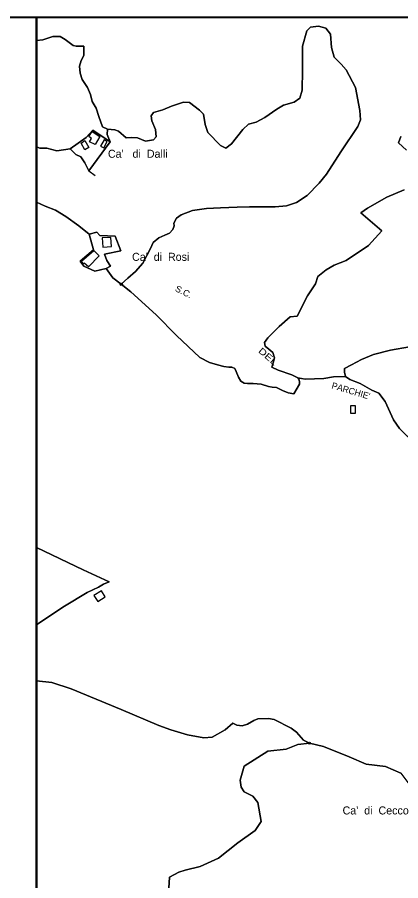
# Model space of a CAD drawing. Extents: x 650468 to 655025, y 889970 to 891591.
# Drawn here: x 653594 to 654074, y 890512 to 891591 of the extents above; entities that cross this region are included whole.
import ezdxf
from ezdxf.enums import TextEntityAlignment as Align

# ---------------------------------------------------------------- set-up
doc = ezdxf.new("R2010")
doc.units = 0
doc.header["$LTSCALE"] = 5.6
doc.header["$PDMODE"] = 32
doc.header["$PDSIZE"] = 2.8
for name, color, linetype, lineweight in [('2', 7, 'Continuous', 25), ('35', 7, 'Continuous', 25), ('36', 7, 'Continuous', 25), ('37', 7, 'Continuous', 25), ('6', 7, 'Continuous', 25), ('61', 7, 'Continuous', 35)]:
    doc.layers.add(name, color=color, linetype=linetype, lineweight=lineweight)
doc.layers.add('60', color=7, linetype='Continuous')

msp = doc.modelspace()

# ---------------------------------------------------------------- linework, layer by layer
at = {"layer": '2'}
for points in [[(653673.57, 891416.45), (653678.66, 891409.08), (653683.47, 891399.15), (653710.23, 891435.25), (653688.69, 891450.13), (653680.38, 891440.64), (653660.36, 891426.81), (653667.27, 891419.45)], [(653683.55, 891441.89), (653687.64, 891448.36), (653697.47, 891442.19), (653691.48, 891431.96), (653684.6, 891435.36), (653686.7, 891439.4)], [(653678.65, 891436.86), (653683.42, 891428.33), (653678.65, 891425.24), (653673.81, 891433.77)], [(653702.8, 891438.01), (653698.29, 891429.97), (653702.15, 891427.86), (653706.43, 891435.83)], [(653700.22, 891315.25), (653701, 891303.93), (653711.74, 891304.65), (653711.13, 891315.64)], [(653689.69, 891299.64), (653696.5, 891292.71), (653683.12, 891279.08), (653677.9, 891283.75), (653677.1, 891282.92), (653674.2, 891286.3)]]:
    msp.add_lwpolyline(points, close=True, dxfattribs=at)
for points in [[(653716.57, 891317.55), (653697.34, 891318.4), (653693.43, 891322.32), (653684.02, 891319.96)], [(653684.02, 891319.96), (653689.25, 891300.36), (653672.79, 891286.24), (653677.47, 891279.85), (653690.97, 891273.65), (653705.37, 891277.05), (653710.67, 891280.15), (653706.27, 891286.95), (653703.07, 891295.15), (653723.73, 891299.05), (653716.57, 891317.55)]]:
    msp.add_lwpolyline(points, dxfattribs=at)
at = {"layer": '35'}
msp.add_lwpolyline([(654084.85, 891179.05), (654060.75, 891174.83), (654039.66, 891169.4), (654024.6, 891163.37), (654011.94, 891156.74), (654003.51, 891151.92), (654003.16, 891147.66), (654004.69, 891141.92), (654010.04, 891138.49), (654023.02, 891133.14), (654037.53, 891125.11), (654046.31, 891121.29), (654054.33, 891110.98), (654064.64, 891088.06), (654072.27, 891076.98), (654082.2, 891067.04)], dxfattribs=at)
msp.add_lwpolyline([(653618.27, 890831.56), (653632.13, 890841.1), (653653.19, 890855.2), (653681.51, 890872.22), (653695.46, 890878.92), (653702.04, 890882.5), (653709.07, 890885.64), (653676.42, 890900.31), (653618.27, 890928.35)], close=True, dxfattribs=at)
at = {"layer": '36'}
for points in [[(654180.27, 891591.08), (653618.27, 891591.08)], [(653618.27, 891591.08), (653618.27, 891561.91), (653626.06, 891562.98), (653638.51, 891567.01), (653647.84, 891567.01), (653654.07, 891563.49), (653663.92, 891555.94), (653667.55, 891554.93), (653677.21, 891555.07), (653677.21, 891543.5), (653674.1, 891536.96), (653672.02, 891529.91), (653672.54, 891521.36), (653675.13, 891513.31), (653681.87, 891503.25), (653685.5, 891494.69), (653687.58, 891485.64), (653692.76, 891477.59), (653696.28, 891467.23), (653700.76, 891454.04), (653706.98, 891451.05), (653715.93, 891450.55), (653720.77, 891448.91), (653730.1, 891440.35), (653736.32, 891440.86), (653744.62, 891440.35), (653754.47, 891436.33), (653764.33, 891437.84), (653767.91, 891441.84), (653766.92, 891450.92), (653762.25, 891461.49), (653761.73, 891468.03), (653764.33, 891472.05), (653776.25, 891475.57), (653787.14, 891480.1), (653802.18, 891485.13), (653809.44, 891484.63), (653821.89, 891475.07), (653827.07, 891470.04), (653829.15, 891456.96)], [(653829.15, 891456.96), (653832.26, 891446.9), (653848.34, 891430.79), (653855.08, 891427.27), (653861.82, 891432.81), (653876.34, 891450.92), (653883.08, 891457.46), (653892.93, 891459.98), (653903.82, 891466.01), (653918.86, 891476.08), (653927.16, 891481.11), (653940.57, 891485.02), (653947.31, 891490.05), (653950.42, 891500.11), (653950.94, 891524.77), (653950.94, 891554.95), (653956.12, 891574.07), (653960.79, 891578.6), (653970.64, 891580.11), (653979.98, 891577.59), (653985.68, 891570.05), (653987.24, 891553.44), (653990.35, 891541.37), (653999.17, 891532.31), (654005.39, 891525.27), (654017.32, 891503.13), (654022.51, 891474.63), (654023.55, 891463.05), (654019.92, 891454.5), (653998.66, 891422.8), (653981.03, 891395.13), (653971.74, 891383.73), (653956.7, 891368.14), (653943.22, 891359.58), (653930.77, 891355.56), (653916.77, 891354.05), (653902.25, 891354.05), (653884.62, 891354.05), (653869.06, 891353.55), (653848.32, 891353.04)], [(654080.73, 891424.8), (654070.84, 891434.15), (654073.82, 891441.86)], [(653935.54, 891216.61), (653944.25, 891217.61), (653956.94, 891242.75), (653966.97, 891257.92), (653970.12, 891267.14), (653980.32, 891275.6), (653990.27, 891281.32), (654005.44, 891287.05), (654033.54, 891305.96), (654049.9, 891324.12), (654023.61, 891346.5), (654032.16, 891352.42), (654056.47, 891366.24), (654078.16, 891375.45)], [(653848.32, 891353.04), (653830.69, 891352.04), (653813.06, 891349.52), (653799.05, 891343.99), (653793.35, 891339.96), (653789.72, 891333.92), (653790.24, 891330.4), (653788.68, 891325.87), (653784.53, 891321.35), (653778.83, 891318.83), (653771.05, 891315.31), (653764.21, 891309.49), (653760.58, 891301.94), (653751.25, 891283.83), (653741.91, 891273.26), (653732.4, 891264.91), (653724.1, 891257.3), (653736.11, 891247.91), (653767.66, 891218.95), (653793.29, 891193.29), (653822.21, 891165.65), (653834.52, 891159.66), (653844.57, 891156.66), (653852.56, 891154.41), (653858.48, 891153.91), (653862.6, 891153.66), (653866.21, 891151.91), (653868.01, 891148.41), (653870.59, 891141.41), (653873.68, 891136.16), (653877.8, 891133.91), (653882.18, 891133.16), (653889.14, 891133.16), (653899.19, 891132.41), (653908.21, 891129.41), (653912.84, 891128.91), (653918.25, 891128.41), (653925.98, 891124.41), (653932.94, 891121.66), (653940.04, 891120.48)], [(653940.04, 891120.48), (653947.23, 891132.4), (653947.23, 891135.93), (653946.33, 891138.55), (653945.13, 891140.59), (653937.62, 891144.09), (653920.51, 891150.2), (653912.46, 891153.63), (653913.96, 891159.1), (653915.63, 891165.59), (653913.56, 891172.13), (653908.89, 891176.16), (653904.23, 891180.18), (653903.19, 891184.71), (653907.34, 891190.24), (653921.62, 891204.42), (653935.54, 891216.61)], [(653786.19, 890700.26), (653771.25, 890705.76), (653723.84, 890725.75), (653661.66, 890751.68), (653637.45, 890759.68), (653618.27, 890761.81), (653618.27, 890249.95)], [(653783.48, 890502.65), (653784.27, 890516.11), (653795.96, 890522.54), (653804.2, 890525.04), (653823.01, 890529.82), (653845.68, 890539.84), (653870.14, 890559.32), (653891.81, 890574.66), (653899.19, 890586), (653894.97, 890609.74), (653888.53, 890617.66), (653878.02, 890622.93), (653874.07, 890628.85), (653872.76, 890637.4), (653878.02, 890655.17), (653907.6, 890673.6), (653930.6, 890676.23), (653945.06, 890682.15), (653959.44, 890683.82), (653952.13, 890687.71), (653943.24, 890697.52), (653936.47, 890702.48), (653915.28, 890713.18), (653908.47, 890714.71), (653894.98, 890714.18), (653889.97, 890712.23), (653882.05, 890707.5), (653875.38, 890705.34), (653868.68, 890706.1), (653863.67, 890708.72), (653854.21, 890700.26), (653837.72, 890691.26), (653827.41, 890690.26), (653806.8, 890694.26), (653786.19, 890700.26)]]:
    msp.add_lwpolyline(points, dxfattribs=at)
at = {"layer": '37'}
msp.add_line((653683.47, 891399.14), (653691.34, 891393.29), dxfattribs=at)
for points in [[(653813.06, 891349.52), (653830.69, 891352.04), (653848.32, 891353.04), (653869.06, 891353.55), (653884.62, 891354.05), (653902.25, 891354.05), (653916.77, 891354.05), (653930.77, 891355.56), (653943.22, 891359.58), (653956.7, 891368.14), (653971.74, 891383.73), (653981.03, 891395.13), (653998.66, 891422.8), (654019.92, 891454.5), (654023.55, 891463.05), (654022.51, 891474.63), (654017.32, 891503.13), (654005.39, 891525.27), (653999.17, 891532.31), (653990.35, 891541.37), (653987.24, 891553.44), (653985.68, 891570.05), (653979.98, 891577.59), (653970.64, 891580.11), (653960.79, 891578.6), (653956.12, 891574.07), (653950.94, 891554.95), (653950.94, 891524.77), (653950.42, 891500.11), (653947.31, 891490.05), (653940.57, 891485.02), (653927.16, 891481.11), (653918.86, 891476.08), (653903.82, 891466.01), (653892.93, 891459.98), (653883.08, 891457.46), (653876.34, 891450.92), (653861.82, 891432.81), (653855.08, 891427.27), (653848.34, 891430.79)], [(653710.23, 891435.24), (653706.68, 891444.44), (653706.98, 891451.05), (653700.76, 891454.04), (653696.28, 891467.23), (653692.76, 891477.59), (653687.58, 891485.64), (653685.5, 891494.69), (653681.87, 891503.25), (653675.13, 891513.31), (653672.54, 891521.36), (653672.02, 891529.91), (653674.1, 891536.96), (653677.21, 891543.5), (653677.21, 891555.07), (653667.55, 891554.93), (653663.92, 891555.94), (653654.07, 891563.49), (653647.84, 891567.01), (653638.51, 891567.01), (653626.06, 891562.98), (653618.27, 891561.91), (653618.27, 891429.1)], [(653848.34, 891430.79), (653832.26, 891446.9), (653829.15, 891456.96), (653827.07, 891470.04), (653821.89, 891475.07), (653809.44, 891484.63), (653802.18, 891485.13), (653787.14, 891480.1), (653776.25, 891475.57), (653764.33, 891472.05), (653761.73, 891468.03), (653762.25, 891461.49), (653766.92, 891450.92), (653767.91, 891441.84), (653764.33, 891437.84), (653754.47, 891436.33), (653744.62, 891440.35), (653736.32, 891440.86), (653730.1, 891440.35), (653720.77, 891448.91), (653715.93, 891450.55), (653706.98, 891451.05)], [(653630.84, 891427.39), (653643.62, 891423.98), (653660.36, 891426.8), (653680.38, 891440.63), (653688.69, 891450.12), (653710.23, 891435.24)], [(653706.98, 891451.05), (653706.68, 891444.44), (653710.23, 891435.24), (653683.47, 891399.14), (653678.66, 891409.07), (653673.57, 891416.44), (653667.27, 891419.44), (653660.36, 891426.8)], [(654073.82, 891441.86), (654070.84, 891434.15), (654080.73, 891424.8)], [(653660.36, 891426.8), (653643.62, 891423.98), (653630.84, 891427.39), (653622.32, 891427.39), (653618.27, 891429.1), (653618.27, 891360.03)], [(653618.27, 891429.1), (653622.32, 891427.39), (653630.84, 891427.39)], [(654078.16, 891375.45), (654056.47, 891366.24), (654032.16, 891352.42), (654023.61, 891346.5)], [(653618.27, 891360.03), (653629.14, 891354.92), (653641.92, 891349.8)], [(653641.92, 891349.8), (653629.14, 891354.92), (653618.27, 891360.03), (653618.27, 890928.35)], [(653641.92, 891349.8), (653654.7, 891342.13), (653670.89, 891330.19), (653684.02, 891319.95), (653693.43, 891322.31)], [(653684.02, 891319.95), (653670.89, 891330.19), (653654.7, 891342.13), (653641.92, 891349.8)], [(653705.37, 891277.04), (653713.5, 891265.39), (653724.1, 891257.3), (653732.4, 891264.91), (653741.91, 891273.26), (653751.25, 891283.83), (653760.58, 891301.94), (653764.21, 891309.49), (653771.05, 891315.31), (653778.83, 891318.83), (653784.53, 891321.35), (653788.68, 891325.87), (653790.24, 891330.4), (653789.72, 891333.92), (653793.35, 891339.96), (653799.05, 891343.99), (653813.06, 891349.52)], [(654023.61, 891346.5), (654049.9, 891324.12), (654033.54, 891305.96), (654005.44, 891287.05), (653990.27, 891281.32), (653980.32, 891275.6), (653970.12, 891267.14), (653966.97, 891257.92), (653956.94, 891242.75), (653944.25, 891217.61), (653935.54, 891216.61), (653921.62, 891204.42), (653907.34, 891190.24), (653903.19, 891184.71), (653904.23, 891180.18), (653908.89, 891176.16), (653913.56, 891172.13), (653915.63, 891165.59), (653913.96, 891159.1), (653912.46, 891153.63), (653920.51, 891150.2), (653937.62, 891144.09), (653945.13, 891140.59)], [(653693.43, 891322.31), (653697.34, 891318.39), (653716.57, 891317.54), (653723.73, 891299.04), (653703.07, 891295.14), (653706.27, 891286.94), (653710.67, 891280.14), (653705.37, 891277.04)], [(653724.1, 891257.3), (653713.5, 891265.39), (653705.37, 891277.04), (653690.97, 891273.64), (653677.47, 891279.84), (653672.79, 891286.23), (653689.25, 891300.35), (653684.02, 891319.95)], [(653705.37, 891277.04), (653713.5, 891265.39), (653724.1, 891257.3)], [(654004.69, 891141.92), (653989.79, 891141.65), (653977.45, 891139.7), (653954.29, 891138.62), (653945.13, 891140.59), (653946.33, 891138.55), (653947.23, 891135.93), (653947.23, 891132.4), (653940.04, 891120.48), (653932.94, 891121.66), (653925.98, 891124.41), (653918.25, 891128.41), (653912.84, 891128.91), (653908.21, 891129.41), (653899.19, 891132.41), (653889.14, 891133.16), (653882.18, 891133.16), (653877.8, 891133.91), (653873.68, 891136.16), (653870.59, 891141.41), (653868.01, 891148.41), (653866.21, 891151.91), (653862.6, 891153.66), (653858.48, 891153.91), (653852.56, 891154.41), (653844.57, 891156.66), (653834.52, 891159.66), (653822.21, 891165.65), (653793.29, 891193.29), (653767.66, 891218.95), (653736.11, 891247.91), (653724.1, 891257.3)], [(654004.69, 891141.92), (654003.16, 891147.66), (654003.51, 891151.92), (654011.94, 891156.74), (654024.6, 891163.37), (654039.66, 891169.4), (654060.75, 891174.83), (654084.85, 891179.05), (654102.33, 891181.46), (654118.59, 891185.08), (654130.65, 891190.5), (654143.3, 891196.53), (654154.75, 891204.37), (654169.81, 891212.81), (654180.66, 891218.84), (654198.73, 891223.66)], [(653945.13, 891140.59), (653954.29, 891138.62), (653977.45, 891139.7), (653989.79, 891141.65), (654004.69, 891141.92)], [(654092.89, 891059.02), (654082.2, 891067.04), (654072.27, 891076.98), (654064.64, 891088.06), (654054.33, 891110.98), (654046.31, 891121.29), (654037.53, 891125.11), (654023.02, 891133.14), (654010.04, 891138.49), (654004.69, 891141.92)], [(653618.27, 890928.35), (653676.42, 890900.31), (653709.07, 890885.64), (653702.04, 890882.5), (653695.46, 890878.92), (653681.51, 890872.22), (653653.19, 890855.2), (653632.13, 890841.1), (653618.27, 890831.56), (653618.27, 890761.81), (653637.45, 890759.68), (653661.66, 890751.68), (653723.84, 890725.75), (653771.25, 890705.76), (653786.19, 890700.26), (653806.8, 890694.26), (653827.41, 890690.26), (653837.72, 890691.26), (653854.21, 890700.26), (653863.67, 890708.72), (653868.68, 890706.1), (653875.38, 890705.34), (653882.05, 890707.5), (653889.97, 890712.23), (653894.98, 890714.18), (653908.47, 890714.71), (653915.28, 890713.18), (653936.47, 890702.48), (653943.24, 890697.52), (653952.13, 890687.71), (653959.44, 890683.82)], [(654073.92, 890646.45), (654054.75, 890654.53), (654030.52, 890657.56), (654009.33, 890666.64), (653977.03, 890679.77), (653959.44, 890683.82), (653945.06, 890682.15), (653930.6, 890676.23), (653907.6, 890673.6), (653878.02, 890655.17), (653872.76, 890637.4), (653874.07, 890628.85), (653878.02, 890622.93), (653888.53, 890617.66), (653894.97, 890609.74), (653899.19, 890586), (653891.81, 890574.66), (653870.14, 890559.32), (653845.68, 890539.84), (653823.01, 890529.82), (653804.2, 890525.04), (653795.96, 890522.54), (653784.27, 890516.11), (653783.48, 890502.65)], [(653959.44, 890683.82), (653977.03, 890679.77), (654009.33, 890666.64), (654030.52, 890657.56), (654054.75, 890654.53), (654073.92, 890646.45), (654085.02, 890631.3), (654097.14, 890614.13), (654111.06, 890601.43), (654122.58, 890590.55), (654129.76, 890584.43)]]:
    msp.add_lwpolyline(points, dxfattribs=at)
for p in [(653724.1, 891257.3), (653959.44, 890683.82)]:
    msp.add_point(p, dxfattribs=at)
at = {"layer": '6'}
for points in [[(654016.84, 891095.84), (654011.24, 891095.84), (654011.24, 891105.84), (654016.84, 891105.84)], [(653699.23, 890874.34), (653690.02, 890868.33), (653694.95, 890860.77), (653704.17, 890866.78)]]:
    msp.add_lwpolyline(points, close=True, dxfattribs=at)
at = {"layer": '61', "lineweight": 40}
for points in [[(653618.27, 891591.08), (653618.27, 889969.62), (652568.28, 889969.62), (652568.28, 891591.08)], [(653618.27, 891591.08), (655025.2, 891591.08), (655025.2, 889969.62), (653618.27, 889969.62)]]:
    msp.add_lwpolyline(points, close=True, dxfattribs=at)

# ---------------------------------------------------------------- texts
at = {"layer": '60'}
for s, p in [("Ca'   di  Dalli", (653744.77, 891415.49)), ("Ca'  di  Rosi", (653773.46, 891286.65)), ("Ca'  di  Cecco", (654042.38, 890594.69))]:
    msp.add_text(s, height=10, dxfattribs=at).set_placement(p, align=Align.CENTER)
for s, rotation, width, p in [('S.C.', 333.419, 1.05, (653800.41, 891244.4)), ('DEL', 319.164, 1.3, (653905.08, 891164.11))]:
    msp.add_text(s, height=8, rotation=rotation, dxfattribs=dict(at, width=width)).set_placement(p, align=Align.CENTER)
msp.add_text("PARCHIE'", height=8, rotation=343.421, dxfattribs=at).set_placement((654010.29, 891120.32), align=Align.CENTER)

doc.saveas('drawing.dxf')
